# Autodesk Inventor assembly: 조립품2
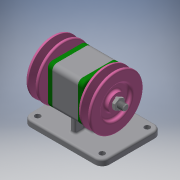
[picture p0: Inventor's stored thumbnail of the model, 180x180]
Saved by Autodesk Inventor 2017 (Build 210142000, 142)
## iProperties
Part Number: 조립품2
Material: 일반
Document SubType Name: Assembly
Designer: 222
Author: 222
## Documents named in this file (10)
- C:\Users\222\Desktop\701106V1042\조립품2.iam
- C:\Users\222\Desktop\701106V1042\701106V1402.ipt
- C:\Users\222\Desktop\701106V1042\축.ipt
- C:\Users\222\Desktop\701106V1042\V-벨트풀리.ipt
- C:\Users\222\Desktop\701106V1042\너트 M10x1.ipt
- C:\Users\222\Desktop\701106V1042\오일 실 17 30 5.ipt
- C:\Users\222\Desktop\701106V1042\베어링 6004.ipt
- C:\Users\222\Desktop\701106V1042\키 5 x 5 x 12.ipt
- C:\Users\222\Desktop\701106V1042\커버.ipt
- C:\Users\222\Desktop\701106V1042\볼트 M4.ipt
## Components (3 placed, 2 different names)
1. 701106V1402:1 — 플러쉬:1
2. V-벨트풀리:2 — 플러쉬:11
3. V-벨트풀리:3 — 플러쉬:10
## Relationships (3: Flush 3)
- 플러쉬:1 [Flush]: 701106V1402:1
- 플러쉬:10 [Flush]: V-벨트풀리:3
- 플러쉬:11 [Flush]: V-벨트풀리:2
